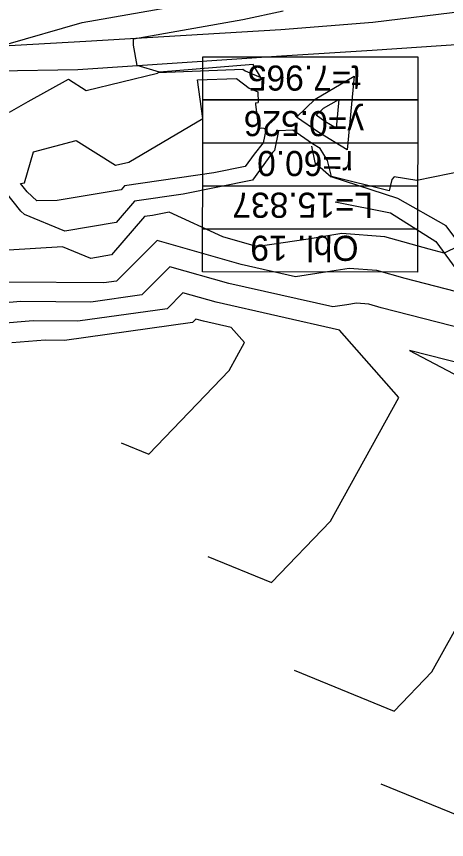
# Model space of a CAD drawing. Extents: x -549394 to -546608, y -1037055 to -1033629.
# Drawn here: x -548340.9 to -548280.9, y -1035658.1 to -1035543.3 of the extents above; entities that cross this region are included whole.
import ezdxf

# ---------------------------------------------------------------- set-up
doc = ezdxf.new("R2010")
doc.units = 0
for name, color, linetype in [('hlavni_vrst', 7, 'Continuous'), ('hrana_L', 7, 'Continuous'), ('norm_vrst', 7, 'Continuous'), ('x_popis_oblouky_C1', 7, 'Continuous')]:
    doc.layers.add(name, color=color, linetype=linetype)

msp = doc.modelspace()

# ---------------------------------------------------------------- linework, layer by layer
at = {"layer": 'hlavni_vrst'}
for p, q in [((-548331.75, -1035544.15), (-548317.15, -1035541.57)), ((-548342.4, -1035547.19), (-548331.75, -1035544.15)), ((-548321.95, -1035571.03), (-548323.04, -1035571.19)), ((-548319.62, -1035570.57), (-548321.95, -1035571.03)), ((-548312.11, -1035574.03), (-548319.62, -1035570.57)), ((-548323.04, -1035571.19), (-548327.66, -1035576.54)), ((-548307.76, -1035575.26), (-548312.11, -1035574.03)), ((-548300.21, -1035574.34), (-548307.2, -1035575.39)), ((-548295.5, -1035573.57), (-548300.21, -1035574.34)), ((-548289.51, -1035574.05), (-548295.5, -1035573.57)), ((-548283.29, -1035575.77), (-548289.51, -1035574.05)), ((-548334.51, -1035575.4), (-548342.05, -1035575.9)), ((-548330.55, -1035577.03), (-548334.51, -1035575.4)), ((-548307.2, -1035575.39), (-548307.76, -1035575.26)), ((-548279.19, -1035575.35), (-548281.19, -1035576.31)), ((-548327.66, -1035576.54), (-548330.55, -1035577.03)), ((-548281.19, -1035576.31), (-548283.29, -1035575.77))]:
    msp.add_line(p, q, dxfattribs=at)
at = {"layer": 'hrana_L'}
for p, q in [((-548264.75, -1035540.94), (-548291.18, -1035544.12)), ((-548291.18, -1035544.12), (-548304, -1035545.14)), ((-548304, -1035545.14), (-548331.23, -1035546.79)), ((-548331.23, -1035546.79), (-548345.31, -1035547.6)), ((-548291.26, -1035548), (-548263.97, -1035546.13)), ((-548303.93, -1035548.8), (-548291.26, -1035548)), ((-548332.34, -1035550.7), (-548303.93, -1035548.8)), ((-548345.16, -1035550.89), (-548332.34, -1035550.7)), ((-548299.75, -1035561.36), (-548299.29, -1035563.67)), ((-548299.29, -1035563.67), (-548297.01, -1035565.68)), ((-548287.66, -1035568.68), (-548297.01, -1035565.68)), ((-548280.93, -1035572.5), (-548287.66, -1035568.68)), ((-548296.43, -1035569.15), (-548288.7, -1035570.68)), ((-548288.7, -1035570.68), (-548282.38, -1035574.67)), ((-548244.89, -1035621.3), (-548280.93, -1035572.5)), ((-548282.38, -1035574.67), (-548265, -1035598.62))]:
    msp.add_line(p, q, dxfattribs=at)
at = {"layer": 'norm_vrst'}
for p, q in [((-548309.32, -1035543.7), (-548303.69, -1035542.5)), ((-548324.57, -1035546.39), (-548309.32, -1035543.7)), ((-548324.56, -1035547.28), (-548324.57, -1035546.39)), ((-548324.05, -1035550.15), (-548324.56, -1035547.28)), ((-548320.96, -1035551.07), (-548324.05, -1035550.15)), ((-548307.86, -1035549.98), (-548320.96, -1035551.07)), ((-548306.82, -1035551.8), (-548307.86, -1035549.98)), ((-548331.19, -1035553.62), (-548321.25, -1035551.22)), ((-548321.25, -1035551.22), (-548321.15, -1035551.16)), ((-548321.15, -1035551.11), (-548309.32, -1035550.64)), ((-548321.15, -1035551.16), (-548321.15, -1035551.11)), ((-548309.32, -1035550.64), (-548309, -1035550.89)), ((-548309, -1035550.89), (-548306.82, -1035551.8)), ((-548339.28, -1035555.15), (-548333.68, -1035552.05)), ((-548333.68, -1035552.05), (-548331.19, -1035553.62)), ((-548315.64, -1035552.13), (-548310.21, -1035551.92)), ((-548314.91, -1035557.52), (-548315.64, -1035552.13)), ((-548310.21, -1035551.92), (-548308.42, -1035553.3)), ((-548299.21, -1035554.83), (-548293.79, -1035551.63)), ((-548293.79, -1035551.63), (-548294.77, -1035561.88)), ((-548308.42, -1035553.3), (-548307.23, -1035553.8)), ((-548307.23, -1035553.8), (-548307.2, -1035555.29)), ((-548301.83, -1035557.32), (-548299.21, -1035554.83)), ((-548298.05, -1035556.1), (-548295.93, -1035554.85)), ((-548295.93, -1035554.85), (-548296.31, -1035558.85)), ((-548341.9, -1035556.62), (-548339.28, -1035555.15)), ((-548307.54, -1035555.32), (-548307.2, -1035555.29)), ((-548307.54, -1035555.32), (-548307.53, -1035555.57)), ((-548307.53, -1035555.57), (-548307.15, -1035558.85)), ((-548299.07, -1035557.07), (-548298.05, -1035556.1)), ((-548297.85, -1035557.92), (-548299.07, -1035557.07)), ((-548325.23, -1035563.59), (-548314.91, -1035557.52)), ((-548298.72, -1035559.49), (-548301.83, -1035557.32)), ((-548296.31, -1035558.85), (-548297.85, -1035557.92)), ((-548307.15, -1035558.85), (-548306.72, -1035558.81)), ((-548306.72, -1035558.81), (-548306.04, -1035558.9)), ((-548306.04, -1035558.9), (-548306.47, -1035560.91)), ((-548304.32, -1035559.22), (-548304.92, -1035561.97)), ((-548302.32, -1035559.16), (-548304.32, -1035559.22)), ((-548299.59, -1035561.06), (-548302.32, -1035559.16)), ((-548294.77, -1035561.88), (-548298.72, -1035559.49)), ((-548338.53, -1035562.18), (-548332.57, -1035560.57)), ((-548332.57, -1035560.57), (-548327.09, -1035564.03)), ((-548340.31, -1035570.43), (-548347.53, -1035561.56)), ((-548306.47, -1035560.91), (-548307.76, -1035562.5)), ((-548298.54, -1035561.7), (-548299.59, -1035561.06)), ((-548297.5, -1035563.39), (-548298.54, -1035561.7)), ((-548339.82, -1035566.51), (-548338.53, -1035562.18)), ((-548307.76, -1035562.5), (-548309.01, -1035564.22)), ((-548305.18, -1035562.28), (-548307.96, -1035566.13)), ((-548304.92, -1035561.97), (-548305.18, -1035562.28)), ((-548327.09, -1035564.03), (-548325.23, -1035563.59)), ((-548296.93, -1035565.6), (-548297.5, -1035563.39)), ((-548313.35, -1035565.08), (-548325.83, -1035566.92)), ((-548309.01, -1035564.22), (-548313.35, -1035565.08)), ((-548275.63, -1035564.26), (-548285.05, -1035566.19)), ((-548307.96, -1035566.13), (-548317.65, -1035568.06)), ((-548288.87, -1035567.62), (-548296.93, -1035565.6)), ((-548288.53, -1035566.05), (-548288.87, -1035567.62)), ((-548288.19, -1035565.64), (-548288.53, -1035566.05)), ((-548285.05, -1035566.19), (-548288.19, -1035565.64)), ((-548340.38, -1035566.59), (-548339.82, -1035566.51)), ((-548339.44, -1035567.74), (-548340.38, -1035566.59)), ((-548326.31, -1035567.47), (-548335.24, -1035568.98)), ((-548325.83, -1035566.92), (-548326.31, -1035567.47)), ((-548338.1, -1035568.99), (-548339.44, -1035567.74)), ((-548317.65, -1035568.06), (-548324.43, -1035569.06)), ((-548335.24, -1035568.98), (-548338.1, -1035568.99)), ((-548324.43, -1035569.06), (-548326.98, -1035572.01)), ((-548339.79, -1035570.92), (-548340.31, -1035570.43)), ((-548334.19, -1035573.23), (-548339.79, -1035570.92)), ((-548326.98, -1035572.01), (-548334.19, -1035573.23)), ((-548321.3, -1035574.56), (-548326.95, -1035580.22)), ((-548309.53, -1035577.89), (-548321.3, -1035574.56)), ((-548301.98, -1035579.6), (-548309.53, -1035577.89)), ((-548319.49, -1035578.2), (-548323.42, -1035582.14)), ((-548311.29, -1035580.53), (-548319.49, -1035578.2)), ((-548297.49, -1035578.92), (-548301.98, -1035579.6)), ((-548294.47, -1035578.43), (-548297.49, -1035578.92)), ((-548290.63, -1035578.74), (-548294.47, -1035578.43)), ((-548286.64, -1035579.84), (-548290.63, -1035578.74)), ((-548326.95, -1035580.22), (-548328.71, -1035580.46)), ((-548276.78, -1035582.39), (-548286.64, -1035579.84)), ((-548328.71, -1035580.46), (-548341.97, -1035580.37)), ((-548296.76, -1035583.8), (-548311.29, -1035580.53)), ((-548323.42, -1035582.14), (-548330.54, -1035583.13)), ((-548317.68, -1035581.85), (-548319.89, -1035584.07)), ((-548313.06, -1035583.16), (-548317.68, -1035581.85)), ((-548340.29, -1035583.06), (-548345.92, -1035583.52)), ((-548330.54, -1035583.13), (-548340.29, -1035583.06)), ((-548295.82, -1035587.05), (-548313.06, -1035583.16)), ((-548294.78, -1035583.51), (-548296.76, -1035583.8)), ((-548293.45, -1035583.29), (-548294.78, -1035583.51)), ((-548291.75, -1035583.43), (-548293.45, -1035583.29)), ((-548289.99, -1035583.91), (-548291.75, -1035583.43)), ((-548319.89, -1035584.07), (-548332.37, -1035585.8)), ((-548272.37, -1035588.47), (-548289.99, -1035583.91)), ((-548338.6, -1035585.75), (-548347.77, -1035586.5)), ((-548332.37, -1035585.8), (-548338.6, -1035585.75)), ((-548315.87, -1035585.5), (-548316.36, -1035586)), ((-548314.83, -1035585.8), (-548315.87, -1035585.5)), ((-548310.95, -1035586.67), (-548314.83, -1035585.8)), ((-548316.36, -1035586), (-548334.2, -1035588.47)), ((-548309.09, -1035588.78), (-548310.95, -1035586.67)), ((-548287.53, -1035596.44), (-548295.82, -1035587.05)), ((-548336.91, -1035588.45), (-548341.57, -1035588.83)), ((-548334.2, -1035588.47), (-548336.91, -1035588.45)), ((-548311.23, -1035592.66), (-548309.09, -1035588.78)), ((-548286.04, -1035589.87), (-548265.57, -1035600.78)), ((-548267.96, -1035594.55), (-548286.04, -1035589.87)), ((-548322.43, -1035604.32), (-548311.23, -1035592.66)), ((-548297.08, -1035613.68), (-548287.53, -1035596.44)), ((-548326.3, -1035602.74), (-548322.43, -1035604.32)), ((-548282.92, -1035634.7), (-548266.31, -1035604.7)), ((-548305.3, -1035622.25), (-548297.08, -1035613.68)), ((-548314.22, -1035618.61), (-548305.3, -1035622.25)), ((-548302.13, -1035634.48), (-548288.18, -1035640.17)), ((-548288.18, -1035640.17), (-548282.92, -1035634.7)), ((-548290.04, -1035650.35), (-548271.05, -1035658.1))]:
    msp.add_line(p, q, dxfattribs=at)
at = {"layer": 'x_popis_oblouky_C1'}
for points in [[(-548284.91, -1035554.94), (-548314.91, -1035554.91), (-548314.9, -1035548.91), (-548284.9, -1035548.94)], [(-548284.91, -1035560.94), (-548314.91, -1035560.91), (-548314.91, -1035554.91), (-548284.91, -1035554.94)], [(-548284.92, -1035566.94), (-548314.92, -1035566.91), (-548314.91, -1035560.91), (-548284.91, -1035560.94)], [(-548284.93, -1035572.94), (-548314.93, -1035572.91), (-548314.92, -1035566.91), (-548284.92, -1035566.94)], [(-548284.93, -1035578.94), (-548314.93, -1035578.91), (-548314.93, -1035572.91), (-548284.93, -1035572.94)]]:
    msp.add_lwpolyline(points, close=True, dxfattribs=at)

# ---------------------------------------------------------------- texts
for s, p in [('t=7.965', (-548292.86, -1035550.14)), ('y=0.526', (-548292.4, -1035556.49)), ('r=60.0', (-548293.92, -1035562.05)), ('L=15.837', (-548291.13, -1035567.88)), ('Obl. 19', (-548293.17, -1035573.88))]:
    msp.add_text(s, height=3.5, rotation=179.9678, dxfattribs=at).set_placement(p)

doc.saveas('drawing.dxf')
